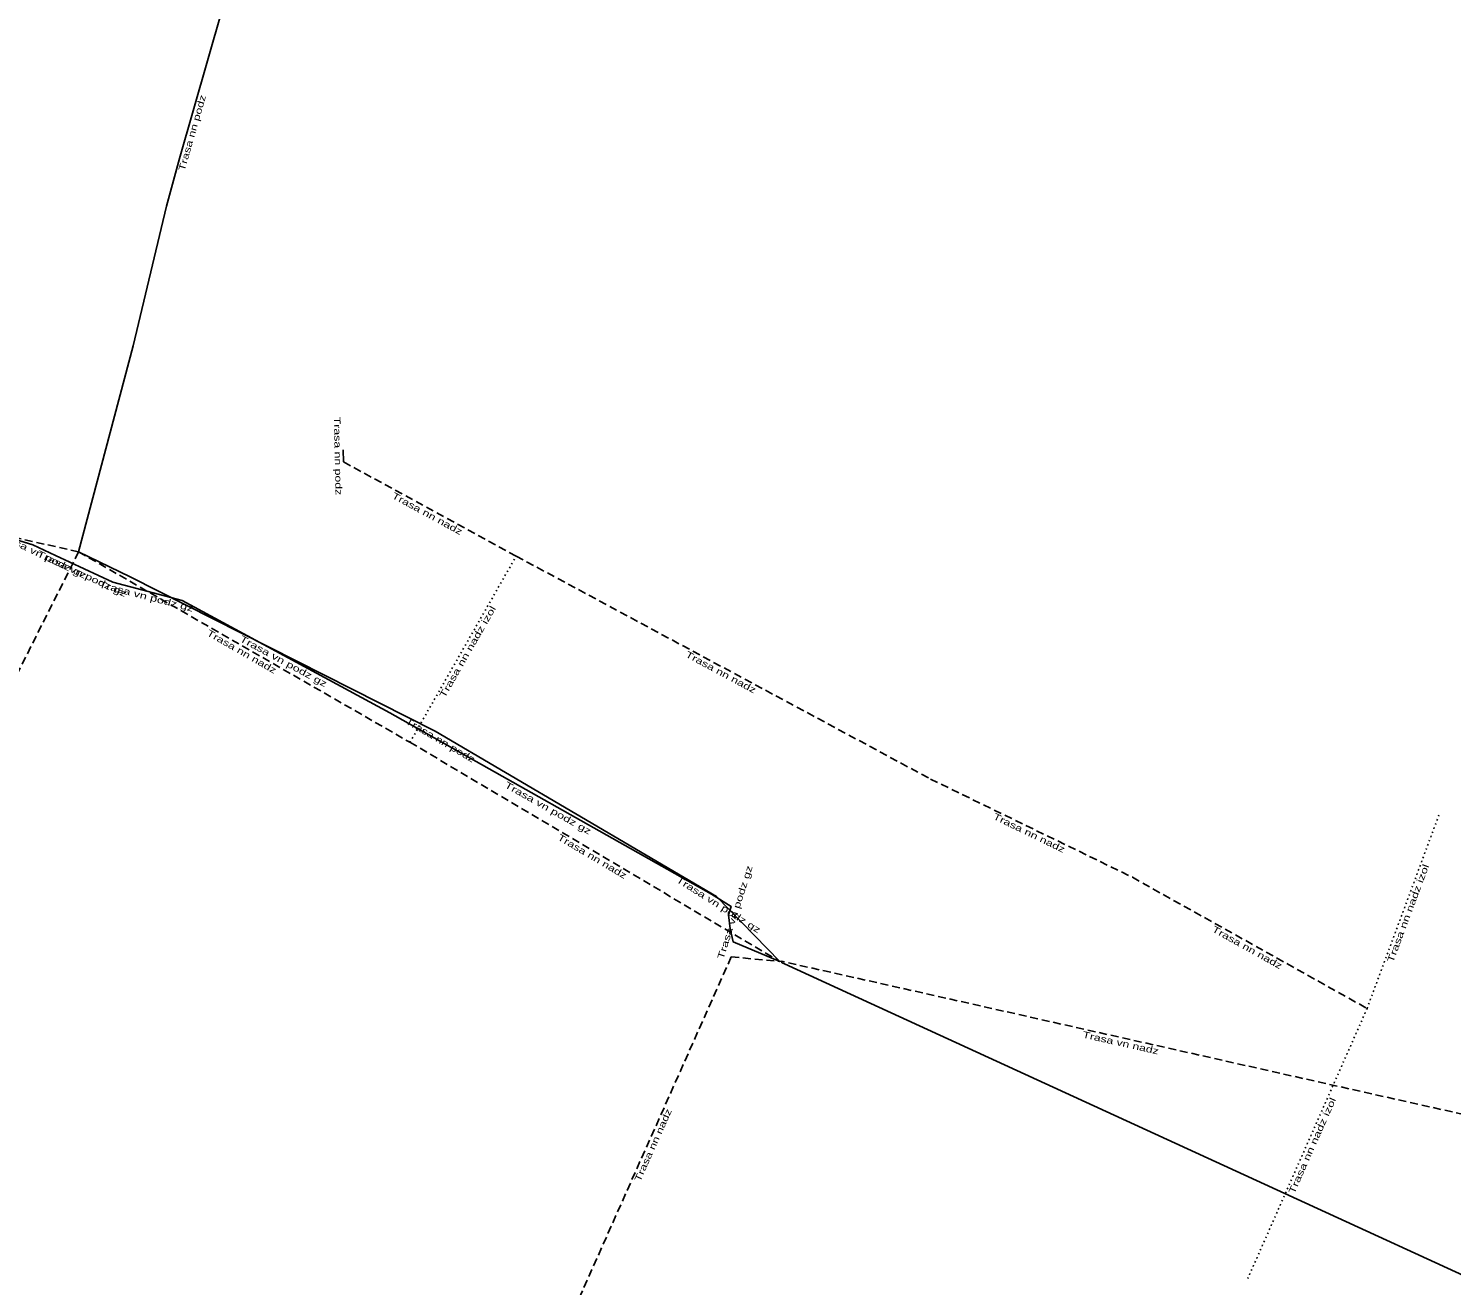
# Model space of a CAD drawing. Extents: x -733620 to -732615, y -1025255 to -1024617.
# Drawn here: x -732923.9 to -732815.4, y -1024868.1 to -1024772.3 of the extents above; entities that cross this region are included whole.
import ezdxf
from ezdxf.enums import TextEntityAlignment as Align

# ---------------------------------------------------------------- set-up
doc = ezdxf.new("R2010")
doc.units = 0
doc.header["$LTSCALE"] = 0.2
doc.linetypes.add('DOTTED', pattern=[1.5, 0.3, -1.2])
doc.linetypes.add('MEDIUM_DASHED', pattern=[4.5, 3, -1.5])
doc.layers.add('11', color=7, linetype='MEDIUM_DASHED', lineweight=25)
doc.layers.add('21', color=7, linetype='Continuous', lineweight=25)
doc.layers.add('20', color=7, linetype='Continuous')

msp = doc.modelspace()

# ---------------------------------------------------------------- linework, layer by layer
at = {"layer": '11', "linetype": 'Continuous'}
msp.add_line((-732899.88, -1024805.31), (-732899.9, -1024804.4), dxfattribs=at)
at = {"layer": '11'}
for p, q in [((-732886.7, -1024812.5), (-732899.88, -1024805.31)), ((-732920.07, -1024812.17), (-732937.4, -1024808.3)), ((-732920.07, -1024812.17), (-732933.38, -1024838.62)), ((-732920.07, -1024812.17), (-732894.8, -1024826.7)), ((-732886.7, -1024812.5), (-732855.1, -1024829.5)), ((-732894.8, -1024826.7), (-732866.592, -1024843.413)), ((-732855.1, -1024829.5), (-732839.7, -1024837)), ((-732839.7, -1024837), (-732821.8, -1024847))]:
    msp.add_line(p, q, dxfattribs=at)
at = {"layer": '11', "linetype": 'DOTTED'}
for p, q in [((-732894.8, -1024826.7), (-732886.7, -1024812.5)), ((-732821.8, -1024847), (-732816.3, -1024832.2)), ((-732821.8, -1024847), (-732830.9, -1024867.6))]:
    msp.add_line(p, q, dxfattribs=at)
at = {"layer": '11', "linetype": 'Continuous'}
for points in [[(-732900.33, -1024749.39), (-732904.84, -1024755.82), (-732912.39, -1024782.18), (-732913.38, -1024785.82), (-732915.9, -1024796.45), (-732920.07, -1024812.17)], [(-732920.07, -1024812.17), (-732916.15, -1024814.09), (-732892.89, -1024825.84), (-732871.41, -1024838.46), (-732866.592, -1024843.413)]]:
    msp.add_lwpolyline(points, dxfattribs=at)
at = {"layer": '11'}
msp.add_lwpolyline([(-732884.46, -1024874.85), (-732870.298, -1024843.067), (-732866.592, -1024843.413)], dxfattribs=at)
at = {"layer": '21'}
for p, q in [((-732923.565, -1024811.633), (-732931.743, -1024809.13)), ((-732923.565, -1024811.633), (-732921.843, -1024812.456)), ((-732912.168, -1024815.873), (-732896.347, -1024824.455)), ((-732896.347, -1024824.455), (-732871.803, -1024838.276)), ((-732871.803, -1024838.276), (-732870.297, -1024839.227)), ((-732870.297, -1024839.227), (-732870.497, -1024839.86))]:
    msp.add_line(p, q, dxfattribs=at)
for points in [[(-732931.743, -1024809.13), (-732923.565, -1024811.633), (-732921.843, -1024812.456), (-732917.459, -1024814.496), (-732912.168, -1024815.873), (-732896.347, -1024824.455), (-732871.803, -1024838.276), (-732870.297, -1024839.227), (-732870.497, -1024839.86), (-732870.381, -1024840.938), (-732870.146, -1024841.921), (-732866.592, -1024843.413)], [(-732921.843, -1024812.456), (-732917.459, -1024814.496), (-732912.168, -1024815.873)], [(-732810.267, -1025254.546), (-732810.793, -1025254.541), (-732868.102, -1025210.744), (-732832.119, -1025143.011), (-732803.544, -1025067.869), (-732774.969, -1024931.344), (-732792.737, -1024877.324), (-732846.364, -1024852.718), (-732861.192, -1024845.915), (-732866.229, -1024843.604), (-732866.41, -1024843.521), (-732866.434, -1024843.521), (-732866.434, -1024843.406), (-732866.592, -1024843.413)]]:
    msp.add_lwpolyline(points, dxfattribs=at)
at = {"layer": '21', "linetype": 'MEDIUM_DASHED'}
msp.add_lwpolyline([(-732814.417, -1024855.094), (-732866.427, -1024843.406), (-732866.592, -1024843.413)], dxfattribs=at)

# ---------------------------------------------------------------- texts
at = {"layer": '20'}
for s, rotation, width, p in [('Trasa nn podz', 74.017, 1.4, (-732911.1715, -1024780.2853)), ('Trasa nn podz', 271.259, 1.4, (-732900.5399, -1024804.869)), ('Trasa nn nadz', 331.386, 1.4, (-732893.6012, -1024809.4755)), ('Trasa vn podz gz', 334.455, 1.45, (-732922.9833, -1024812.6304)), ('Trasa vn podz gz', 335.046, 1.45, (-732919.925, -1024814.0653)), ('Trasa vn podz gz', 345.412, 1.45, (-732914.9765, -1024815.8132)), ('Trasa nn nadz izol', 60.299, 1.45, (-732890.185, -1024819.9214)), ('Trasa nn nadz', 330.102, 1.4, (-732907.7581, -1024819.9978)), ('Trasa vn podz gz', 331.523, 1.45, (-732904.5667, -1024820.7357)), ('Trasa nn nadz', 331.721, 1.4, (-732871.2079, -1024821.5711)), ('Trasa nn podz', 329.565, 1.4, (-732892.6161, -1024826.7541)), ('Trasa vn podz gz', 330.616, 1.45, (-732884.3932, -1024831.9317)), ('Trasa nn nadz', 334.033, 1.4, (-732847.684, -1024833.8343)), ('Trasa nn nadz', 329.353, 1.4, (-732881.0269, -1024835.6152)), ('Trasa nn nadz izol', 69.614, 1.45, (-732818.4399, -1024839.8256)), ('Trasa vn podz gz', 327.729, 1.45, (-732871.397, -1024839.3007)), ('Trasa vn podz gz', 72.466, 1.45, (-732869.7767, -1024839.7388)), ('Trasa nn nadz', 330.81, 1.4, (-732831.0664, -1024842.5673)), ('Trasa vn nadz', 347.335, 1.4, (-732840.6443, -1024849.8651)), ('Trasa nn nadz izol', 66.167, 1.45, (-732825.7548, -1024857.5625)), ('Trasa nn nadz', 65.982, 1.4, (-732876.0273, -1024857.5233))]:
    msp.add_text(s, height=0.5, rotation=rotation, dxfattribs=dict(at, width=width)).set_placement(p, align=Align.CENTER)

doc.saveas('drawing.dxf')
